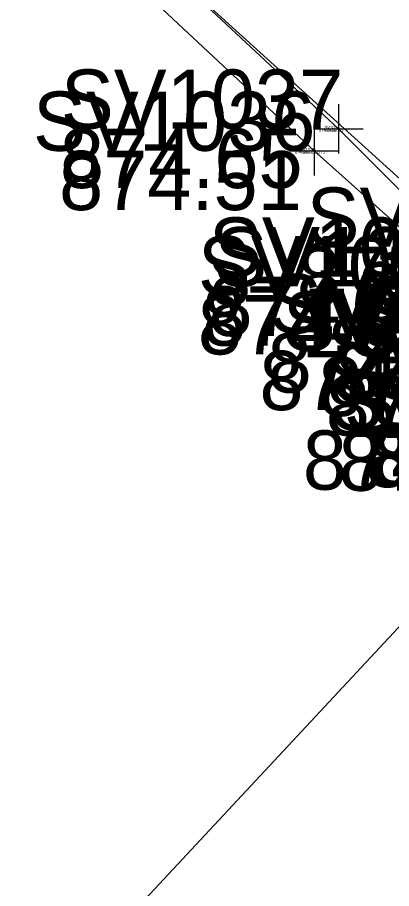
# Model space of a CAD drawing. Extents: x 1475918 to 1480402, y 379235 to 383359.
# Drawn here: x 1480200.92 to 1480208.48, y 379404.92 to 379422.56 of the extents above; entities that cross this region are included whole.
import ezdxf

# ---------------------------------------------------------------- set-up
doc = ezdxf.new("R2010")
doc.units = 0
for name, color, linetype in [('PM_X_Crosswalk', 7, 'Continuous'), ('PV_X_Curb', 7, 'Continuous'), ('SV_X_Shot_Marker', 7, 'Continuous'), ('SV_X_Text_Comment', 7, 'Continuous'), ('SV_X_Text_Elevation', 7, 'Continuous'), ('SV_X_Text_Name', 7, 'Continuous'), ('UT_X_Water', 7, 'Continuous')]:
    doc.layers.add(name, color=color, linetype=linetype)

msp = doc.modelspace()

# ---------------------------------------------------------------- linework, layer by layer
at = {"layer": 'PM_X_Crosswalk'}
msp.add_line((1480185.279, 379385.114), (1480212.329, 379414.193), dxfattribs=at)
at = {"layer": 'PV_X_Curb'}
for points in [[(1480186.975, 379439.363), (1480207.407, 379420.301), (1480210.41, 379417.305), (1480211.712, 379416.16), (1480212.774, 379415.29), (1480213.67, 379414.243), (1480215.361, 379412.945), (1480216.632, 379411.517), (1480217.745, 379410.456), (1480218.76, 379409.536), (1480221.908, 379406.565), (1480233.156, 379396.15)], [(1480186.493, 379438.955), (1480206.919, 379419.855), (1480210.187, 379416.932), (1480211.433, 379415.804), (1480213.11, 379414.171), (1480218.471, 379409.217), (1480217.005, 379410.473), (1480215.222, 379412.175), (1480221.495, 379406.235), (1480232.955, 379395.538)]]:
    msp.add_lwpolyline(points, dxfattribs=at)
at = {"layer": 'SV_X_Shot_Marker'}
for p, q in [((1480207.407, 379420.801), (1480207.407, 379419.801)), ((1480206.907, 379420.301), (1480207.907, 379420.301)), ((1480206.919, 379420.355), (1480206.919, 379419.355)), ((1480207.389, 379420.318), (1480207.425, 379420.284)), ((1480207.424, 379420.32), (1480207.39, 379420.283)), ((1480207.407, 379420.301), (1480207.407, 379420.301)), ((1480207.407, 379420.301), (1480207.407, 379420.301)), ((1480206.419, 379419.855), (1480207.419, 379419.855)), ((1480206.901, 379419.872), (1480206.938, 379419.838)), ((1480206.936, 379419.874), (1480206.902, 379419.837)), ((1480206.919, 379419.855), (1480206.919, 379419.855)), ((1480206.919, 379419.855), (1480206.919, 379419.855))]:
    msp.add_line(p, q, dxfattribs=at)
at = {"layer": 'UT_X_Water'}
msp.add_lwpolyline([(1480049.152, 379568.017), (1480068.611, 379550.193), (1480086.403, 379533.424), (1480090.024, 379530.079), (1480102.295, 379519.134), (1480111.734, 379511.473), (1480120.332, 379509.136), (1480127.535, 379501.668), (1480127.911, 379496.395), (1480140.166, 379484.084), (1480149.088, 379474.708), (1480164.726, 379459.482), (1480172.622, 379452.503), (1480197.813, 379429.111), (1480212.628, 379415.684), (1480231.592, 379398.237)], dxfattribs=at)

# ---------------------------------------------------------------- texts
at = {"layer": 'SV_X_Text_Comment'}
for s, p in [('C1', (1480207.407, 379420.241)), ('GUT1', (1480206.919, 379419.795))]:
    msp.add_text(s, height=0.06, dxfattribs=at).set_placement(p)
at = {"layer": 'SV_X_Text_Elevation'}
for s, height, p in [('874.65', 1.2, (1480201.776, 379419.101)), ('874.6536', 0.06, (1480207.017, 379420.241)), ('874.65', 0.06, (1480207.125, 379420.241)), ('874.51', 1.2, (1480201.758, 379418.655)), ('874.5050', 0.06, (1480206.524, 379419.795)), ('874.51', 0.06, (1480206.661, 379419.795)), ('875.00', 1.2, (1480206.566, 379416.712)), ('875.07', 1.2, (1480207.803, 379416.398)), ('874.67', 1.2, (1480204.779, 379416.105)), ('874.60', 1.2, (1480204.651, 379415.91)), ('874.62', 1.2, (1480204.565, 379415.732)), ('874.90', 1.2, (1480205.977, 379414.96)), ('874.97', 1.2, (1480207.334, 379414.751)), ('874.64', 1.2, (1480205.811, 379414.604)), ('874.94', 1.2, (1480207.006, 379414.484)), ('874.94', 1.2, (1480207.152, 379414.09)), ('874.80', 1.2, (1480207.954, 379413.043)), ('874.80', 1.2, (1480208.093, 379413.08)), ('874.69', 1.2, (1480206.688, 379412.993)), ('874.70', 1.2, (1480207.413, 379412.971))]:
    msp.add_text(s, height=height, dxfattribs=at).set_placement(p)
at = {"layer": 'SV_X_Text_Name'}
for s, height, p in [('SV1037', 1.2, (1480201.795, 379420.301)), ('SV1036', 1.2, (1480201.232, 379419.855)), ('SV1037', 0.06, (1480207.127, 379420.301)), ('SV1037', 0.06, (1480207.126, 379420.301)), ('SV1036', 0.06, (1480206.635, 379419.855)), ('SV1036', 0.06, (1480206.635, 379419.855)), ('SV1330', 1.2, (1480206.765, 379417.912)), ('SV1038', 1.2, (1480204.789, 379417.305)), ('SV1329', 1.2, (1480204.897, 379417.11)), ('SV1039', 1.2, (1480204.566, 379416.932)), ('SV1040', 1.2, (1480206.006, 379416.16)), ('SV1188', 1.2, (1480207.949, 379415.951)), ('SV1041', 1.2, (1480206.282, 379415.804)), ('SV1148', 1.2, (1480207.603, 379415.684)), ('SV1043', 1.2, (1480207.172, 379415.29)), ('SV1210', 1.2, (1480207.238, 379414.193)), ('SV1042', 1.2, (1480207.517, 379414.171)), ('SV1044', 1.2, (1480208.077, 379414.243))]:
    msp.add_text(s, height=height, dxfattribs=at).set_placement(p)

doc.saveas('drawing.dxf')
